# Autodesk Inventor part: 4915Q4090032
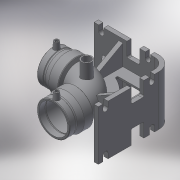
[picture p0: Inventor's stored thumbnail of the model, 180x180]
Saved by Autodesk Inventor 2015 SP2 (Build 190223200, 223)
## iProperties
Created: 2017-06
Part Number: 4915Q4090032
Material: Generic
Description: PLASSON DF 90° ELBOW 90-32-90 WITH OUTLET
Document SubType Name: Modeling
Designer: KIM
Mass: 55.0731 g
Surface Area: 148.067 cm^2
Volume: 55.0731 cm^3
Density: 1 g/cm^3
Appearance: Default
Author: KIM
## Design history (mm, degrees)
derived "4915Q4.ipt"
feature "Solid1::4915Q4.ipt"
tag "TaggingFeature1"
body "Solid1"
other parameters: "d14" = 17.6296, "d19" = 3.52592, "d20" = 168 deg, "d22" = 103.04, "d23" = 112, "d24" = 99.9488, "d29" = 71, "d35" = 15, "d39" = 5 deg, "d45" = 4, "d46" = 14, "d47" = 0, "d63" = 147, "d67" = 45 deg, "d71" = 90 deg, "d75" = 5.6, "d82" = 45 deg, "d83" = 69, "d84" = 100.8, "d87" = 26.1, "d88" = 26.1, "d90" = 13.05, "d91" = 33.6, "d92" = 156.8, "d93" = 0, "d94" = 26.1, "d95" = 26.1, "d96" = 50 deg, "d98" = 145.34, "d99" = 5.6, "d100" = 0, "d101" = 4.5, "d102" = 22.4, "d103" = 11.2, "d104" = 11.2, "d105" = 13.05, "d106" = 0, "d107" = 45 deg, "d108" = 33.6, "d110" = 40.19528, "d111" = 146, "d112" = 16, "d113" = 16.8, "d114" = 22.4, "d116" = 0, "d117" = 4.5, "d118" = 115, "d119" = 115, "d122" = 32, "d124" = 0, "d125" = 25.6, "d127" = 0, "d128" = 3, "d129" = 0, "d130" = 20.01, "d131" = 5.0025, "d132" = 20 deg, "L_0" = 203, "L_1" = 69, "D_" = 112, "A_" = 71, "d_2" = 12, "L_" = 261, "H_" = 146, "A_1" = 115, "d_1" = 32, "d97" = 111.8, "d120" = 262
